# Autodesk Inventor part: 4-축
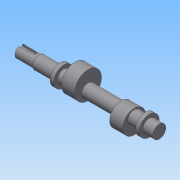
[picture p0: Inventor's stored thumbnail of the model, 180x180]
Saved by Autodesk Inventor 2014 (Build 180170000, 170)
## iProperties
Created: 2014-12
Part Number: 4-축
Material: 일반
Document SubType Name: Modeling
Designer: Owner
Density: 1 g/cm^3
Appearance: 기본값
Author: Owner
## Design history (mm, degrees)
sketch "스케치1"
  geometry: L1 (-90, 0)-(90, 0); L2 (-90, 0)-(-90, 7.5); L3 (-90, 7.5)-(-66, 7.5); L4 (-66, 7.5)-(-66, 8.5); L5 (-66, 8.5)-(-39, 8.5); L6 (-39, 8.5)-(-39, 13); L7 (-39, 13)-(-34, 13); L8 (-34, 13)-(-34, 8.5); L9 (72, 8.5)-(72, 13); L10 (72, 13)-(77, 13); L11 (77, 13)-(77, 8.5); L12 (77, 8.5)-(90, 8.5); L13 (90, 8.5)-(90, 0); L14 (-34, 8.5)-(72, 8.5); 2 further points
  constraints: 28 end point, 7 parallel, 3 perpendicular, 1 coincident, 1 horizontal, 1 midpoint
  dimensions: "d0" = 180 distance between parallel lines of L13 L2; "d1" = 24 distance between parallel lines of L4 L2; "d2" = 27 distance between parallel lines of L6 L4; "d3" = 5 distance between parallel lines of L8 L6; "d4" = 5 distance between parallel lines of L11 L9; "d5" = 13 distance between parallel lines of L13 L11; "d6" = 17 diameter of L12 L1; "d8" = 17 diameter of L5 L1; "d9" = 15 diameter of L3 L1; "d10" = 26 diameter of L7 L1; "d11" = 26 diameter of L10 L1; "d12" = 17 diameter of L14 L1
revolve "회전1" sketch "스케치1" stored, may be unused: angle "d13" = 90 deg
node "작업 평면1"
sketch "스케치2"
  geometry: L1 (-12, -7.5)-(-12, 7.5) reference; L2 (-12, 2.5)-(5.5, 2.5); L3 (5.5, -2.5)-(-12, -2.5); A1 r 2.5 centre (5.5, 0) between (5.5, -2.5) and (5.5, 2.5); 2 further points
  constraints: 4 end point, 2 perpendicular, 2 point on circle, 2 point on line, 2 tangent, 1 centre point, 1 horizontal alignment, 1 midpoint
  dimensions: "d14" = 5 distance between parallel lines of L3 L2; "d15" = 20 dimension on A1 L1
extrude "돌출1" cut sketch "스케치2" distance "d16" = 3; taper "d17" = 0 deg
node "작업 평면2"
sketch "스케치3"
  geometry: C1 r 17.5 at (6, 0); 1 further point
  constraints: 1 centre point, 1 horizontal alignment
  dimensions: "d19" = 35 diameter of C1; "d20" = 6 distance of point (0, 0) C1.centre
extrude "돌출2" join sketch "스케치3" distance "d21" = 17; taper "d22" = 0 deg
node "작업 평면3"
sketch "스케치4"
  geometry: C1 r 15 at (5, 0); 1 further point
  constraints: 1 centre point, 1 horizontal alignment
  dimensions: "d24" = 30 diameter of C1; "d25" = 5 distance of point (0, 0) C1.centre
extrude "돌출3" join sketch "스케치4" distance "d26" = 17; taper "d27" = 0 deg
node "솔리드1"
other parameters: "d18" = -70.5, "d23" = -32.5
